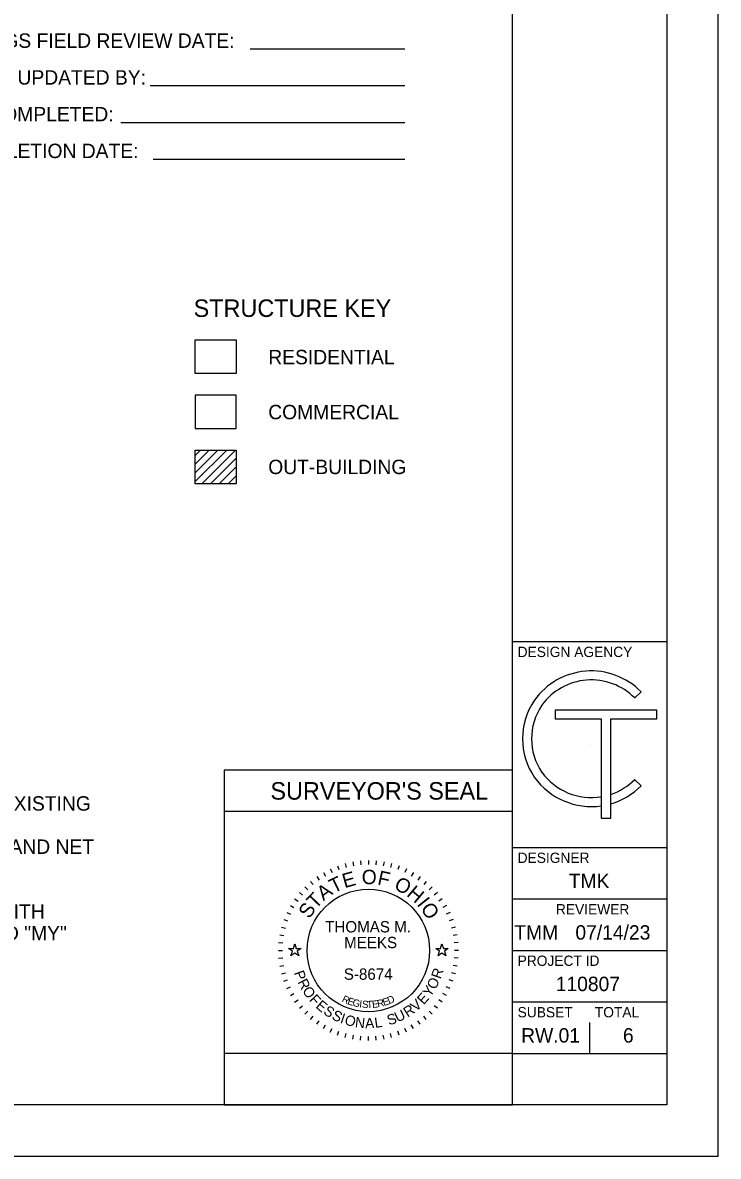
# Model space of a CAD drawing. Extents: x 0 to 34, y 0 to 22.
# Drawn here: x 27.24 to 34, y 0 to 11.01 of the extents above; entities that cross this region are included whole.
import ezdxf

# ---------------------------------------------------------------- set-up
doc = ezdxf.new("R2010")
doc.units = 0
for name, color, linetype in [('Default', 7, 'Continuous'), ('SC_Shading1', 7, 'Continuous'), ('SH_Border', 7, 'Continuous'), ('SH_Cut_Line', 7, 'Continuous'), ('SH_Data', 7, 'Continuous'), ('SH_Text', 7, 'Continuous')]:
    doc.layers.add(name, color=color, linetype=linetype)

msp = doc.modelspace()

# ---------------------------------------------------------------- linework, layer by layer
at = {"layer": 'Default'}
for points in [[(29.824, 2.02), (29.871, 2.02), (29.885, 2.065), (29.899, 2.02), (29.946, 2.02), (29.908, 1.992), (29.923, 1.948), (29.885, 1.975), (29.847, 1.948), (29.862, 1.992)], [(31.254, 2.02), (31.301, 2.02), (31.315, 2.065), (31.329, 2.02), (31.376, 2.02), (31.338, 1.992), (31.353, 1.948), (31.315, 1.975), (31.277, 1.948), (31.292, 1.992)]]:
    msp.add_lwpolyline(points, close=True, dxfattribs=at)
at = {"layer": 'SC_Shading1'}
msp.add_lwpolyline([(28.918, 7.069), (29.315, 7.069), (29.315, 7.395), (28.918, 7.395)], close=True, dxfattribs=at)
at = {"layer": 'SH_Border'}
for p, q in [((32, 0.5), (32, 21.5)), ((32, 5), (33.5, 5)), ((32, 3), (33.5, 3)), ((32, 2.5), (33.5, 2.5)), ((32, 2), (33.5, 2)), ((32, 1.5), (33.5, 1.5)), ((32, 1), (33.5, 1))]:
    msp.add_line(p, q, dxfattribs=at)
msp.add_lwpolyline([(1.5, 21.5), (33.5, 21.5), (33.5, 0.5), (1.5, 0.5)], close=True, dxfattribs=at)
at = {"layer": 'SH_Cut_Line'}
msp.add_lwpolyline([(0, 0), (34, 0), (34, 22), (0, 22)], close=True, dxfattribs=at)
at = {"layer": 'SH_Data'}
for p, q in [((32.75, 4), (32.75, 4)), ((32, 3.75), (29.2, 3.75)), ((29.2, 3.75), (29.2, 0.5)), ((32, 0.5), (32, 3.75)), ((32, 0.5), (32, 3.75)), ((32, 3.35), (29.2, 3.35)), ((30.524, 2.872), (30.527, 2.832)), ((30.6, 2.875), (30.6, 2.835)), ((30.676, 2.872), (30.673, 2.832)), ((30.163, 2.758), (30.183, 2.723)), ((30.23, 2.793), (30.247, 2.757)), ((30.301, 2.822), (30.314, 2.785)), ((30.374, 2.845), (30.384, 2.807)), ((30.448, 2.862), (30.455, 2.822)), ((30.752, 2.862), (30.745, 2.822)), ((30.826, 2.845), (30.816, 2.807)), ((30.899, 2.822), (30.886, 2.785)), ((30.97, 2.793), (30.953, 2.757)), ((31.037, 2.758), (31.017, 2.723)), ((30.038, 2.67), (30.063, 2.64)), ((30.098, 2.717), (30.121, 2.684)), ((31.102, 2.717), (31.079, 2.684)), ((31.162, 2.67), (31.137, 2.64)), ((29.93, 2.562), (29.96, 2.537)), ((29.981, 2.619), (30.01, 2.59)), ((31.219, 2.619), (31.19, 2.59)), ((31.27, 2.562), (31.24, 2.537)), ((29.842, 2.438), (29.877, 2.418)), ((29.883, 2.502), (29.916, 2.479)), ((31.317, 2.502), (31.284, 2.479)), ((31.358, 2.438), (31.323, 2.418)), ((29.807, 2.37), (29.843, 2.353)), ((31.393, 2.37), (31.357, 2.353)), ((29.755, 2.226), (29.793, 2.216)), ((29.778, 2.299), (29.815, 2.286)), ((31.422, 2.299), (31.385, 2.286)), ((31.445, 2.226), (31.407, 2.216)), ((29.738, 2.152), (29.778, 2.145)), ((31.462, 2.152), (31.422, 2.145)), ((29.725, 2), (29.765, 2)), ((29.728, 2.076), (29.768, 2.073)), ((31.472, 2.076), (31.432, 2.073)), ((31.475, 2), (31.435, 2)), ((29.728, 1.924), (29.768, 1.927)), ((31.472, 1.924), (31.432, 1.927)), ((29.738, 1.848), (29.778, 1.855)), ((29.755, 1.774), (29.793, 1.784)), ((31.445, 1.774), (31.407, 1.784)), ((31.462, 1.848), (31.422, 1.855)), ((29.778, 1.701), (29.815, 1.714)), ((31.422, 1.701), (31.385, 1.714)), ((29.807, 1.63), (29.843, 1.647)), ((29.842, 1.563), (29.877, 1.583)), ((31.358, 1.563), (31.323, 1.583)), ((31.393, 1.63), (31.357, 1.647)), ((29.883, 1.498), (29.916, 1.521)), ((29.93, 1.438), (29.96, 1.463)), ((31.27, 1.438), (31.24, 1.463)), ((31.317, 1.498), (31.284, 1.521)), ((29.981, 1.381), (30.01, 1.41)), ((30.038, 1.33), (30.063, 1.36)), ((31.162, 1.33), (31.137, 1.36)), ((31.219, 1.381), (31.19, 1.41)), ((30.098, 1.283), (30.121, 1.316)), ((30.163, 1.242), (30.183, 1.277)), ((30.23, 1.207), (30.247, 1.243)), ((30.301, 1.178), (30.314, 1.215)), ((30.899, 1.178), (30.886, 1.215)), ((30.97, 1.207), (30.953, 1.243)), ((31.037, 1.242), (31.017, 1.277)), ((31.102, 1.283), (31.079, 1.316)), ((32.75, 1), (32.75, 1.3)), ((30.374, 1.155), (30.384, 1.193)), ((30.448, 1.138), (30.455, 1.178)), ((30.524, 1.128), (30.527, 1.168)), ((30.6, 1.125), (30.6, 1.165)), ((30.676, 1.128), (30.673, 1.168)), ((30.752, 1.138), (30.745, 1.178)), ((30.826, 1.155), (30.816, 1.193)), ((32, 0.5), (29.2, 0.5)), ((32, 0.5), (29.2, 0.5))]:
    msp.add_line(p, q, dxfattribs=at)
msp.add_lwpolyline([(32, 0.5), (32, 1), (29.2, 1), (29.2, 0.5)], close=True, dxfattribs=at)
msp.add_circle((30.6, 2), 0.595, dxfattribs=at)
at = {"layer": 'SH_Text'}
for p, q in [((29.45, 10.758), (30.953, 10.758)), ((28.48, 10.401), (30.953, 10.401)), ((28.195, 10.044), (30.953, 10.044)), ((28.51, 9.687), (30.953, 9.687)), ((28.918, 6.858), (28.919, 6.86)), ((28.918, 6.808), (28.969, 6.86)), ((28.918, 6.724), (29.054, 6.86)), ((28.918, 6.639), (29.138, 6.86)), ((28.918, 6.554), (29.223, 6.86)), ((28.982, 6.534), (29.308, 6.86)), ((29.067, 6.534), (29.315, 6.782)), ((29.151, 6.534), (29.315, 6.697)), ((29.236, 6.534), (29.315, 6.612)), ((28.918, 6.538), (28.922, 6.534)), ((33.249, 4.513), (33.187, 4.452)), ((33.249, 4.513), (33.187, 4.452)), ((33.402, 4.333), (32.414, 4.333)), ((32.414, 4.333), (32.414, 4.251)), ((33.402, 4.251), (33.402, 4.333)), ((32.414, 4.251), (32.863, 4.251)), ((32.863, 4.251), (32.863, 3.285)), ((32.956, 3.285), (32.956, 4.251)), ((32.956, 4.251), (33.402, 4.251)), ((33.187, 3.66), (33.249, 3.599)), ((33.187, 3.66), (33.249, 3.599)), ((32.863, 3.493), (32.863, 3.405)), ((32.863, 3.493), (32.863, 3.405)), ((32.956, 3.425), (32.956, 3.516)), ((32.956, 3.425), (32.956, 3.516)), ((32.863, 3.285), (32.956, 3.285))]:
    msp.add_line(p, q, dxfattribs=at)
for points in [[(28.918, 7.93), (29.315, 7.93), (29.315, 7.605), (28.918, 7.605)], [(28.918, 6.86), (29.315, 6.86), (29.315, 6.534), (28.918, 6.534)], [(32.863, 4.251), (32.863, 3.285), (32.956, 3.285), (32.956, 4.251), (33.402, 4.251), (33.402, 4.333), (32.414, 4.333), (32.414, 4.251)]]:
    msp.add_lwpolyline(points, close=True, dxfattribs=at)
for centre, radius, start, end in [((32.766, 4.035), 0.68, 44.7027, 144.3276), ((32.766, 4.035), 0.68, 44.7027, 144.3276), ((32.766, 4.035), 0.593, 44.7362, 144.1102), ((32.766, 4.035), 0.593, 44.7362, 144.1102), ((32.764, 4.056), 0.666, 145.7329, 214.2671), ((32.764, 4.056), 0.666, 145.7329, 214.2671), ((32.764, 4.056), 0.579, 145.7266, 214.2734), ((32.764, 4.056), 0.579, 145.7266, 214.2734), ((32.766, 4.078), 0.68, 215.6724, 278.2613), ((32.766, 4.078), 0.68, 215.6724, 278.2613), ((32.766, 4.078), 0.593, 215.8898, 279.4882), ((32.766, 4.078), 0.593, 215.8898, 279.4882), ((32.766, 4.078), 0.593, 288.6992, 315.2638), ((32.766, 4.078), 0.593, 288.6992, 315.2638), ((32.766, 4.078), 0.68, 286.2291, 315.2973), ((32.766, 4.078), 0.68, 286.2291, 315.2973)]:
    msp.add_arc(centre, radius, start, end, dxfattribs=at)

# ---------------------------------------------------------------- texts
at = {"layer": 'SH_Data'}
for s, height, p in [('DESIGN AGENCY', 0.1, (32.05, 4.85)), ("SURVEYOR'S SEAL", 0.17, (29.648, 3.465)), ('I HAVE REESTABLISHED THE LOCATIONS OF THE EXISTING PROPERTY LINES, THE EXISTING CENTERLINE RIGHT OF WAY, AND THE EXISTING', 0.14, (14.869, 3.358)), ('ESTABLISHED THE PROPOSED PROPERTY LINES, CALCULATED THE GROSS TAKE, PRESENT ROADWAY OCCUPIED (PRO), NET TAKE AND NET', 0.14, (14.869, 2.938)), ('DESIGNER', 0.1, (32.05, 2.85)), ('TMK', 0.14, (32.547, 2.605)), ('DEPARTMENT OF TRANSPORTATION DATED 09-22-2010. ALL OF MY WORK CONTAINED HEREIN WAS CONDUCTED IN ACCORDANCE WITH', 0.14, (14.869, 2.308)), ('REVIEWER', 0.1, (32.422, 2.35)), ('THE OHIO ADMINISTRATIVE CODE CHAPTER 4733-37 STANDARDS FOR BOUNDARY SURVEYS, UNLESS SO NOTED. THE WORDS "I" AND "MY"', 0.14, (14.869, 2.098)), ('THOMAS M.', 0.11, (30.18, 2.175)), ('TMM', 0.14, (32.017, 2.105)), ('07/14/23', 0.14, (32.611, 2.105)), ('MEEKS', 0.11, (30.364, 2.022)), ('PROJECT ID', 0.1, (32.05, 1.85)), ('S-8674', 0.11, (30.361, 1.715)), ('110807', 0.14, (32.42, 1.605)), ('SUBSET', 0.1, (32.05, 1.35)), ('TOTAL', 0.1, (32.8, 1.35)), ('RW.01', 0.14, (32.084, 1.105)), ('6', 0.14, (33.073, 1.105))]:
    msp.add_text(s, height=height, dxfattribs=at).set_placement(p)
for s, height, rotation, p in [('E', 0.14, 15.7571, (30.368, 2.604)), ('O', 0.14, 359.7812, (30.535, 2.644)), ('F', 0.14, 347.4362, (30.681, 2.642)), ('T', 0.14, 25.7167, (30.262, 2.552)), ('O', 0.14, 332.2586, (30.84, 2.602)), ('T', 0.14, 46.4344, (30.088, 2.396)), ('A', 0.14, 36.4747, (30.163, 2.478)), ('H', 0.14, 319.9136, (30.963, 2.536)), ('S', 0.14, 57.1924, (30.028, 2.301)), ('I', 0.14, 308.367, (31.066, 2.448)), ('O', 0.14, 303.1491, (31.102, 2.409)), ('P', 0.1, 289.7431, (29.875, 1.784)), ('R', 0.1, 70.983, (31.301, 1.717)), ('R', 0.1, 296.9802, (29.909, 1.693)), ('Y', 0.1, 55.5058, (31.2, 1.54)), ('O', 0.1, 62.7428, (31.25, 1.613)), ('O', 0.1, 304.7158, (29.953, 1.608)), ('F', 0.1, 312.956, (30.019, 1.516)), ('R', 0.07, 334.487, (30.337, 1.505)), ('E', 0.07, 341.04, (30.391, 1.48)), ('E', 0.07, 17.6836, (30.75, 1.46)), ('D', 0.07, 23.3052, (30.801, 1.477)), ('E', 0.1, 48.2687, (31.137, 1.467)), ('E', 0.1, 319.6885, (30.081, 1.45)), ('S', 0.1, 326.9255, (30.155, 1.389)), ('G', 0.07, 347.4752, (30.441, 1.462)), ('I', 0.07, 353.7858, (30.509, 1.447)), ('S', 0.07, 356.8926, (30.536, 1.443)), ('T', 0.07, 3.0061, (30.586, 1.439)), ('E', 0.07, 6.0117, (30.639, 1.441)), ('R', 0.07, 11.9184, (30.692, 1.447)), ('R', 0.1, 33.296, (30.981, 1.347)), ('V', 0.1, 41.0316, (31.061, 1.401)), ('S', 0.1, 334.1626, (30.236, 1.337)), ('I', 0.1, 341.3997, (30.319, 1.298)), ('O', 0.1, 345.1351, (30.362, 1.282)), ('N', 0.1, 353.3752, (30.466, 1.255)), ('A', 0.1, 1.1108, (30.569, 1.244)), ('L', 0.1, 8.3479, (30.666, 1.247)), ('S', 0.1, 18.3234, (30.8, 1.271)), ('U', 0.1, 25.5604, (30.883, 1.299))]:
    msp.add_text(s, height=height, rotation=rotation, dxfattribs=at).set_placement(p)
at = {"layer": 'SH_Text'}
for s, height, p in [('TRACINGS FIELD REVIEW DATE:', 0.14, (26.356, 10.768)), ('OWNERSHIP UPDATED BY:', 0.14, (25.984, 10.411)), ('DATE COMPLETED:', 0.14, (26.356, 10.054)), ('PLAN COMPLETION DATE:', 0.14, (25.984, 9.697)), ('STRUCTURE KEY', 0.17, (28.902, 8.154)), ('RESIDENTIAL', 0.14, (29.627, 7.694)), ('COMMERCIAL', 0.14, (29.627, 7.16)), ('OUT-BUILDING', 0.14, (29.627, 6.627))]:
    msp.add_text(s, height=height, dxfattribs=at).set_placement(p)

doc.saveas('drawing.dxf')
